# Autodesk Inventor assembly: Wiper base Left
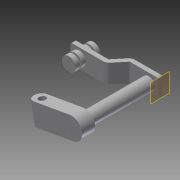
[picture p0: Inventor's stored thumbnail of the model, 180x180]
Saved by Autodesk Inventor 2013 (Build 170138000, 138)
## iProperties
Created: 2006-03
Part Number: Wiper base Left
Document SubType Name: Assembly
Designer: Autodesk, Inc.
Mass: 378.494 g
Surface Area: 188.994 cm^2
Volume: 48.8379 cm^3
Density: 7.75 g/cm^3
Author: Autodesk, Inc.
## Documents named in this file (5)
- C:\Users\boganb\Documents\B2 Design\Goodyear\2013 Tutorial Files\Dynamic Simulation 4\Components\Wiper base Left.iam
- C:\Users\boganb\Documents\B2 Design\Goodyear\2013 Tutorial Files\Dynamic Simulation 4\Components\Axis_Left.ipt
- C:\Users\boganb\Documents\B2 Design\Goodyear\2013 Tutorial Files\Dynamic Simulation 4\Components\Crank_left.ipt
- C:\Users\boganb\Documents\B2 Design\Goodyear\2013 Tutorial Files\Dynamic Simulation 4\Components\Wiper Support.ipt
- C:\Users\boganb\Documents\B2 Design\Goodyear\2013 Tutorial Files\Dynamic Simulation 4\Components\Pawn.ipt
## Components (5 placed, 4 different names)
1. Crank_left:1 — Mate:31, Mate:32, Mate:33, Mate:34, Mate:35, Mate:36, Insert:1
2. Axis_Left:1 — Mate:17, Flush:3, Angle:8, Mate:34, Mate:35, Mate:36
3. Wiper Support:1 — Mate:17, Flush:3, Angle:8
4. Pawn:2 — Insert:1, Insert:2
5. Pawn:1 — Insert:2
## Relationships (11: Mate 7, Insert 2, Flush 1, Angle 1)
- Mate:17: Axis_Left:1 ↔ Wiper Support:1
- Flush:3: Axis_Left:1 ↔ Wiper Support:1
- Angle:8: Axis_Left:1 ↔ Wiper Support:1
- Mate:31: Crank_left:1
- Mate:32: Crank_left:1
- Mate:33: Crank_left:1
- Mate:34: Crank_left:1 ↔ Axis_Left:1
- Mate:35: Crank_left:1 ↔ Axis_Left:1
- Mate:36: Crank_left:1 ↔ Axis_Left:1
- Insert:1: Crank_left:1 ↔ Pawn:2
- Insert:2: Pawn:2 ↔ Pawn:1
